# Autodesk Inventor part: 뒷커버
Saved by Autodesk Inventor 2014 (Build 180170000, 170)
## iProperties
Created: 2025-06
Part Number: 뒷커버
Material: 일반
Document SubType Name: Modeling
Designer: dg
Density: 1 g/cm^3
Appearance: 기본값
Author: dg
Author: jhkim
Creation Date: 2025-05-23
Sending System: Autodesk Inventor 2026
Preprocessor: ST-DEVELOPER v20.1
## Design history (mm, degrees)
node "뒷커버1"
node "솔리드1"
node "기준1"
